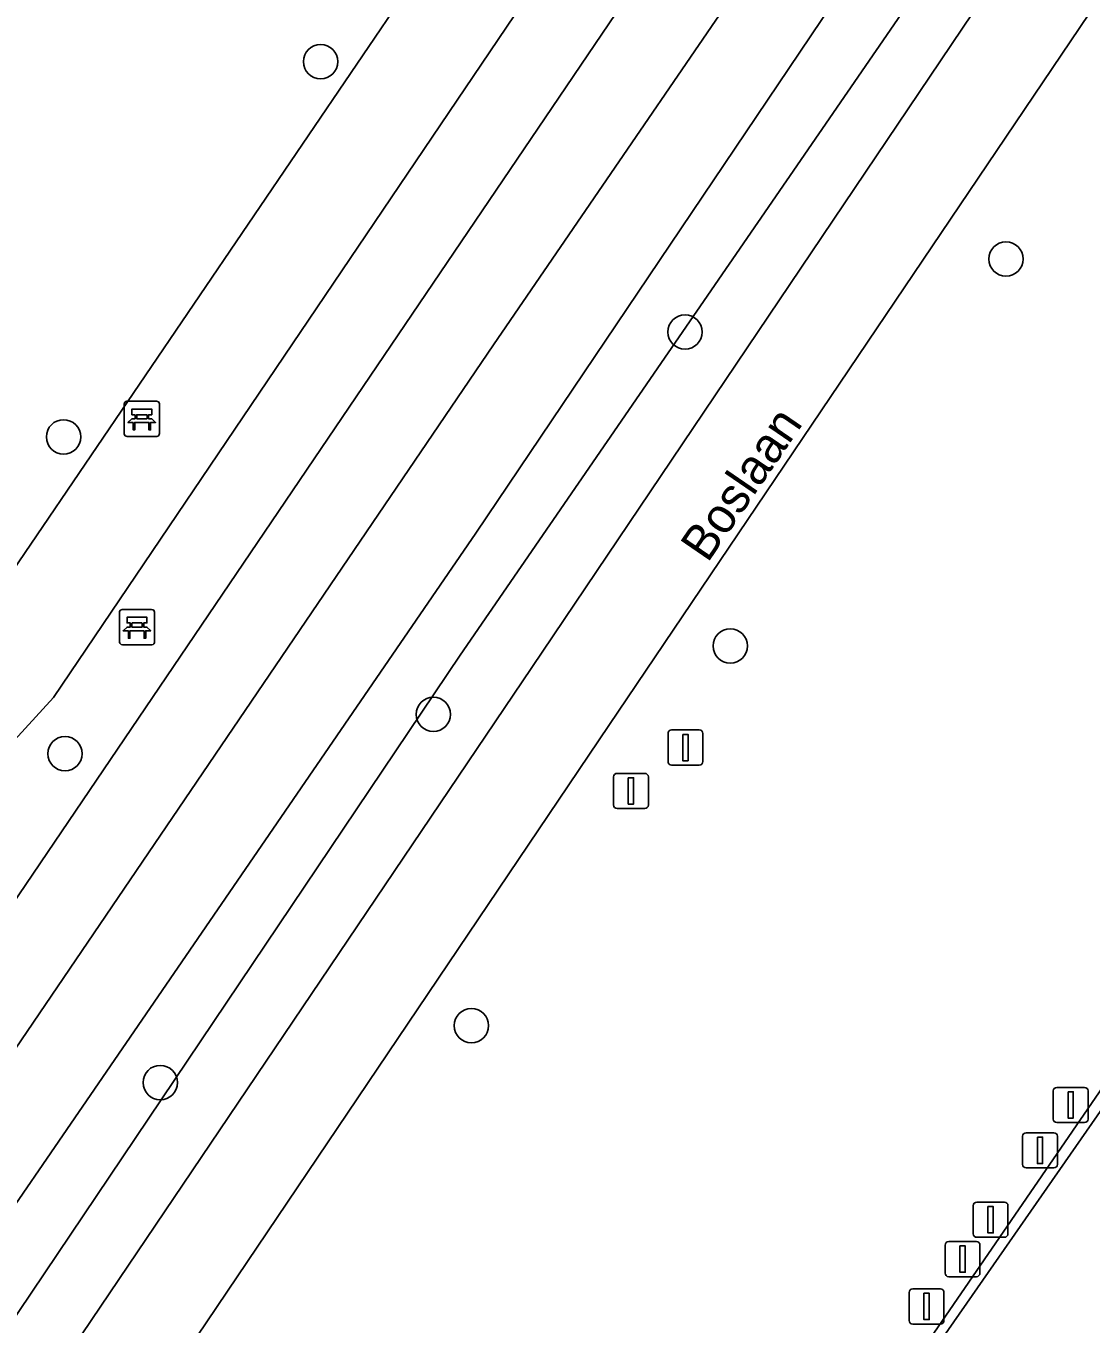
# Model space of a CAD drawing. Extents: x 157132 to 159279, y 384991 to 386650.
# Drawn here: x 159110.16 to 159140.46, y 385090.09 to 385127.03 of the extents above; entities that cross this region are included whole.
import ezdxf

# ---------------------------------------------------------------- set-up
doc = ezdxf.new("R2010")
doc.units = 0
for name, color, linetype in [('IMGEO_Afsluitpaal', 7, 'Continuous'), ('IMGEO_Bank', 7, 'Continuous'), ('IMGEO_Berm_groen', 7, 'Continuous'), ('IMGEO_Boom', 7, 'Continuous'), ('IMGEO_Gemengd_bos', 7, 'Continuous'), ('IMGEO_Grasland_overig', 7, 'Continuous'), ('IMGEO_Lichtmast', 7, 'Continuous'), ('IMGEO_Oever', 7, 'Continuous'), ('IMGEO_Openbare_ruimte_label', 7, 'Continuous'), ('IMGEO_Rijbaan_lokaal_gesloten', 7, 'Continuous'), ('IMGEO_Rijbaan_lokaal_halfverhard', 7, 'Continuous'), ('IMGEO_Voetpad_halfverhard', 7, 'Continuous'), ('IMGEO_Waterloop', 7, 'Continuous')]:
    doc.layers.add(name, color=color, linetype=linetype)

msp = doc.modelspace()

# ---------------------------------------------------------------- linework, layer by layer
at = {"layer": 'IMGEO_Afsluitpaal'}
for p, q in [((159139.391, 385095.925), (159139.391, 385096.725)), ((159139.391, 385096.725), (159139.391, 385095.925)), ((159139.491, 385096.825), (159140.281, 385096.825)), ((159140.281, 385096.825), (159139.491, 385096.825)), ((159140.381, 385096.725), (159140.381, 385095.925)), ((159140.381, 385095.925), (159140.381, 385096.725)), ((159140.281, 385095.825), (159139.491, 385095.825)), ((159139.491, 385095.825), (159140.281, 385095.825)), ((159138.518, 385094.634), (159138.518, 385095.434)), ((159138.518, 385095.434), (159138.518, 385094.634)), ((159138.618, 385095.534), (159139.408, 385095.534)), ((159139.408, 385095.534), (159138.618, 385095.534)), ((159139.508, 385095.434), (159139.508, 385094.634)), ((159139.508, 385094.634), (159139.508, 385095.434)), ((159139.408, 385094.534), (159138.618, 385094.534)), ((159138.618, 385094.534), (159139.408, 385094.534)), ((159137.112, 385092.659), (159137.112, 385093.459)), ((159137.112, 385093.459), (159137.112, 385092.659)), ((159137.212, 385093.559), (159138.002, 385093.559)), ((159138.002, 385093.559), (159137.212, 385093.559)), ((159138.102, 385093.459), (159138.102, 385092.659)), ((159138.102, 385092.659), (159138.102, 385093.459)), ((159136.315, 385091.539), (159136.315, 385092.339)), ((159136.315, 385092.339), (159136.315, 385091.539)), ((159136.415, 385092.439), (159137.205, 385092.439)), ((159137.205, 385092.439), (159136.415, 385092.439)), ((159138.002, 385092.559), (159137.212, 385092.559)), ((159137.212, 385092.559), (159138.002, 385092.559)), ((159137.305, 385092.339), (159137.305, 385091.539)), ((159137.305, 385091.539), (159137.305, 385092.339)), ((159137.205, 385091.439), (159136.415, 385091.439)), ((159136.415, 385091.439), (159137.205, 385091.439)), ((159135.29, 385090.191), (159135.29, 385090.991)), ((159135.29, 385090.991), (159135.29, 385090.191)), ((159135.39, 385091.091), (159136.18, 385091.091)), ((159136.18, 385091.091), (159135.39, 385091.091)), ((159136.28, 385090.991), (159136.28, 385090.191)), ((159136.28, 385090.191), (159136.28, 385090.991)), ((159136.18, 385090.091), (159135.39, 385090.091)), ((159135.39, 385090.091), (159136.18, 385090.091))]:
    msp.add_line(p, q, dxfattribs=at)
for points in [[(159139.811, 385096.7), (159139.961, 385096.7), (159139.961, 385095.95), (159139.811, 385095.95), (159139.811, 385096.7)], [(159138.938, 385095.409), (159139.088, 385095.409), (159139.088, 385094.659), (159138.938, 385094.659), (159138.938, 385095.409)], [(159137.532, 385093.434), (159137.682, 385093.434), (159137.682, 385092.684), (159137.532, 385092.684), (159137.532, 385093.434)], [(159136.735, 385092.314), (159136.885, 385092.314), (159136.885, 385091.564), (159136.735, 385091.564), (159136.735, 385092.314)], [(159135.71, 385090.966), (159135.86, 385090.966), (159135.86, 385090.216), (159135.71, 385090.216), (159135.71, 385090.966)]]:
    msp.add_lwpolyline(points, dxfattribs=at)
for centre, start, end in [((159139.491, 385096.725), 90, 180), ((159139.491, 385096.725), 90, 180), ((159140.281, 385096.725), 0, 90), ((159140.281, 385096.725), 360, 90), ((159139.491, 385095.925), 180, 270), ((159139.491, 385095.925), 180, 270), ((159140.281, 385095.925), 270, 0), ((159140.281, 385095.925), 270, 0), ((159138.618, 385095.434), 90, 180), ((159138.618, 385095.434), 90, 180), ((159139.408, 385095.434), 0, 90), ((159139.408, 385095.434), 360, 90), ((159138.618, 385094.634), 180, 270), ((159138.618, 385094.634), 180, 270), ((159139.408, 385094.634), 270, 0), ((159139.408, 385094.634), 270, 0), ((159137.212, 385093.459), 90, 180), ((159137.212, 385093.459), 90, 180), ((159138.002, 385093.459), 0, 90), ((159138.002, 385093.459), 360, 90), ((159137.212, 385092.659), 180, 270), ((159137.212, 385092.659), 180, 270), ((159138.002, 385092.659), 270, 0), ((159138.002, 385092.659), 270, 0), ((159136.415, 385092.339), 90, 180), ((159136.415, 385092.339), 90, 180), ((159137.205, 385092.339), 0, 90), ((159137.205, 385092.339), 360, 90), ((159136.415, 385091.539), 180, 270), ((159136.415, 385091.539), 180, 270), ((159137.205, 385091.539), 270, 0), ((159137.205, 385091.539), 270, 0), ((159135.39, 385090.991), 90, 180), ((159135.39, 385090.991), 90, 180), ((159136.18, 385090.991), 0, 90), ((159136.18, 385090.991), 360, 90), ((159135.39, 385090.191), 180, 270), ((159135.39, 385090.191), 180, 270), ((159136.18, 385090.191), 270, 0), ((159136.18, 385090.191), 270, 0)]:
    msp.add_arc(centre, 0.1, start, end, dxfattribs=at)
at = {"layer": 'IMGEO_Bank'}
for p, q in [((159112.958, 385115.424), (159112.958, 385116.265)), ((159112.958, 385116.265), (159112.958, 385115.424)), ((159113.033, 385116.349), (159113.874, 385116.349)), ((159113.874, 385116.349), (159113.033, 385116.349)), ((159113.958, 385116.274), (159113.958, 385115.433)), ((159113.958, 385115.433), (159113.958, 385116.274)), ((159113.267, 385115.855), (159113.267, 385115.961)), ((159113.311, 385115.961), (159113.311, 385115.855)), ((159113.599, 385115.967), (159113.317, 385115.967)), ((159113.605, 385115.855), (159113.605, 385115.961)), ((159113.649, 385115.961), (159113.649, 385115.855)), ((159113.655, 385115.747), (159113.262, 385115.747)), ((159113.317, 385115.849), (159113.599, 385115.849)), ((159113.883, 385115.349), (159113.042, 385115.349)), ((159113.042, 385115.349), (159113.883, 385115.349)), ((159112.896, 385110.422), (159113.737, 385110.422)), ((159113.737, 385110.422), (159112.896, 385110.422)), ((159113.821, 385110.347), (159113.821, 385109.506)), ((159113.821, 385109.506), (159113.821, 385110.347)), ((159112.821, 385109.497), (159112.821, 385110.338)), ((159112.821, 385110.338), (159112.821, 385109.497)), ((159113.13, 385109.928), (159113.13, 385110.034)), ((159113.174, 385110.034), (159113.174, 385109.928)), ((159113.462, 385110.04), (159113.18, 385110.04)), ((159113.468, 385109.928), (159113.468, 385110.034)), ((159113.512, 385110.034), (159113.512, 385109.928)), ((159113.518, 385109.82), (159113.125, 385109.82)), ((159113.18, 385109.922), (159113.462, 385109.922)), ((159113.746, 385109.422), (159112.905, 385109.422)), ((159112.905, 385109.422), (159113.746, 385109.422))]:
    msp.add_line(p, q, dxfattribs=at)
for points in [[(159113.261, 385115.967), (159113.175, 385115.967), (159113.175, 385116.128), (159113.738, 385116.128), (159113.738, 385115.967), (159113.655, 385115.967)], [(159113.205, 385115.747), (159113.063, 385115.747), (159113.175, 385115.849), (159113.261, 385115.849)], [(159113.255, 385115.74), (159113.255, 385115.533), (159113.212, 385115.533), (159113.212, 385115.74)], [(159113.655, 385115.849), (159113.738, 385115.849), (159113.85, 385115.747), (159113.711, 385115.747)], [(159113.705, 385115.74), (159113.705, 385115.533), (159113.661, 385115.533), (159113.661, 385115.74)], [(159113.124, 385110.04), (159113.038, 385110.04), (159113.038, 385110.201), (159113.601, 385110.201), (159113.601, 385110.04), (159113.518, 385110.04)], [(159113.068, 385109.82), (159112.926, 385109.82), (159113.038, 385109.922), (159113.124, 385109.922)], [(159113.118, 385109.813), (159113.118, 385109.606), (159113.075, 385109.606), (159113.075, 385109.813)], [(159113.518, 385109.922), (159113.601, 385109.922), (159113.713, 385109.82), (159113.574, 385109.82)], [(159113.568, 385109.813), (159113.568, 385109.606), (159113.524, 385109.606), (159113.524, 385109.813)]]:
    msp.add_lwpolyline(points, dxfattribs=at)
for centre, radius, start, end in [((159113.036, 385116.271), 0.0779, 92.4484, 184.2845), ((159113.036, 385116.271), 0.0779, 92.4484, 184.2845), ((159113.88, 385116.271), 0.0779, 2.4484, 94.2845), ((159113.88, 385116.271), 0.0779, 2.4484, 94.2845), ((159113.26, 385115.96), 0.00671, 2.8957, 87.1043), ((159113.317, 385115.96), 0.00671, 92.8957, 177.1043), ((159113.599, 385115.96), 0.00671, 2.8957, 87.1043), ((159113.656, 385115.96), 0.00671, 92.8957, 177.1043), ((159113.205, 385115.74), 0.00671, 2.8957, 87.1043), ((159113.262, 385115.74), 0.00671, 92.8957, 177.1043), ((159113.26, 385115.856), 0.00671, 272.8957, 357.1043), ((159113.317, 385115.856), 0.00671, 182.8957, 267.1043), ((159113.599, 385115.856), 0.00671, 272.8957, 357.1043), ((159113.656, 385115.856), 0.00671, 182.8957, 267.1043), ((159113.654, 385115.74), 0.00671, 2.8957, 87.1043), ((159113.711, 385115.74), 0.00671, 92.8957, 177.1043), ((159113.036, 385115.427), 0.0779, 182.4484, 274.2845), ((159113.036, 385115.427), 0.0779, 182.4484, 274.2845), ((159113.88, 385115.427), 0.0779, 272.4484, 4.2845), ((159113.88, 385115.427), 0.0779, 272.4484, 4.2845), ((159112.899, 385110.344), 0.0779, 92.4484, 184.2845), ((159112.899, 385110.344), 0.0779, 92.4484, 184.2845), ((159113.743, 385110.344), 0.0779, 2.4484, 94.2845), ((159113.743, 385110.344), 0.0779, 2.4484, 94.2845), ((159113.123, 385110.033), 0.00671, 2.8957, 87.1043), ((159113.18, 385110.033), 0.00671, 92.8957, 177.1043), ((159113.462, 385110.033), 0.00671, 2.8957, 87.1043), ((159113.519, 385110.033), 0.00671, 92.8957, 177.1043), ((159113.068, 385109.813), 0.00671, 2.8957, 87.1043), ((159113.125, 385109.813), 0.00671, 92.8957, 177.1043), ((159113.123, 385109.929), 0.00671, 272.8957, 357.1043), ((159113.18, 385109.929), 0.00671, 182.8957, 267.1043), ((159113.462, 385109.929), 0.00671, 272.8957, 357.1043), ((159113.519, 385109.929), 0.00671, 182.8957, 267.1043), ((159113.517, 385109.813), 0.00671, 2.8957, 87.1043), ((159113.574, 385109.813), 0.00671, 92.8957, 177.1043), ((159112.899, 385109.5), 0.0779, 182.4484, 274.2845), ((159112.899, 385109.5), 0.0779, 182.4484, 274.2845), ((159113.743, 385109.5), 0.0779, 272.4484, 4.2845), ((159113.743, 385109.5), 0.0779, 272.4484, 4.2845)]:
    msp.add_arc(centre, radius, start, end, dxfattribs=at)
at = {"layer": 'IMGEO_Berm_groen'}
for points in [[(159202.762, 385214.209), (159200.279, 385212.099), (159197.861, 385209.917), (159197.685, 385209.729), (159188.555, 385198.998), (159187.341, 385197.178), (159184.592, 385192.9), (159180.472, 385186.763), (159159.585, 385155.808), (159126.749, 385107.119), (159084.716, 385044.777), (159082.453, 385041.511)], [(159077.406, 385029.667), (159079.783, 385025.279), (159082.757, 385021.889), (159087.555, 385018.32), (159091.697, 385024.574), (159107.34, 385047.66), (159126.391, 385075.847), (159142.886, 385099.88), (159158.832, 385122.656), (159159.356, 385123.396), (159166.375, 385133.305), (159172.319, 385141.694), (159187.24, 385161.886), (159198.852, 385176.747), (159203.242, 385182.186)]]:
    msp.add_lwpolyline(points, dxfattribs=at)
at = {"layer": 'IMGEO_Boom'}
for centre in [(159118.543, 385126.012), (159138.044, 385120.396), (159128.913, 385118.319), (159111.23, 385115.335), (159130.199, 385109.386), (159121.753, 385107.439), (159111.272, 385106.32), (159122.836, 385098.582), (159113.982, 385096.963)]:
    msp.add_circle(centre, 0.489, dxfattribs=at)
at = {"layer": 'IMGEO_Gemengd_bos'}
msp.add_lwpolyline([(159105.65, 385105.454), (159139.674, 385155.54), (159093.89, 385177.901)], dxfattribs=at)
at = {"layer": 'IMGEO_Grasland_overig'}
msp.add_lwpolyline([(159098.089, 385179.186), (159097.378, 385179.59), (159094.91, 385178.395), (159093.89, 385177.901), (159139.674, 385155.54), (159105.65, 385105.454), (159098.404, 385096.707), (159088.982, 385080.864), (159077.358, 385063.69), (159069.845, 385053.174), (159071.504, 385050.354), (159072.28, 385049.465), (159088.429, 385074.259), (159094.892, 385087.522), (159100.866, 385096.897), (159110.945, 385107.918), (159129.681, 385135.667), (159170.435, 385195.371), (159173.484, 385199.281), (159170.983, 385201.616), (159141.072, 385157.596)], close=True, dxfattribs=at)
for points in [[(159178.365, 385194.724), (159173.484, 385199.281), (159170.435, 385195.371), (159129.681, 385135.667), (159110.945, 385107.918), (159100.866, 385096.897), (159094.892, 385087.522), (159088.429, 385074.259), (159072.28, 385049.465), (159074.647, 385046.84)], [(159074.812, 385050.814), (159099.176, 385086.396), (159137.123, 385142.415), (159170.631, 385192.472)], [(159076.939, 385044.887), (159078.948, 385043.251), (159079.888, 385042.589), (159124.552, 385108.774), (159157.303, 385157.398), (159178.092, 385188.144), (159178.542, 385188.806), (159179.206, 385191.452)], [(159177.304, 385190.183), (159158.739, 385162.357), (159136.9, 385130.044), (159122.513, 385109.122), (159095.149, 385068.441), (159079.233, 385045.507)]]:
    msp.add_lwpolyline(points, dxfattribs=at)
at = {"layer": 'IMGEO_Lichtmast'}
for p, q in [((159128.43, 385106.096), (159128.43, 385106.896)), ((159128.43, 385106.896), (159128.43, 385106.096)), ((159128.53, 385106.996), (159129.32, 385106.996)), ((159129.32, 385106.996), (159128.53, 385106.996)), ((159129.42, 385106.896), (159129.42, 385106.096)), ((159129.42, 385106.096), (159129.42, 385106.896)), ((159129.32, 385105.996), (159128.53, 385105.996)), ((159128.53, 385105.996), (159129.32, 385105.996)), ((159126.879, 385104.861), (159126.879, 385105.661)), ((159126.879, 385105.661), (159126.879, 385104.861)), ((159126.979, 385105.761), (159127.769, 385105.761)), ((159127.769, 385105.761), (159126.979, 385105.761)), ((159127.869, 385105.661), (159127.869, 385104.861)), ((159127.869, 385104.861), (159127.869, 385105.661)), ((159127.769, 385104.761), (159126.979, 385104.761)), ((159126.979, 385104.761), (159127.769, 385104.761))]:
    msp.add_line(p, q, dxfattribs=at)
for points in [[(159128.85, 385106.871), (159129, 385106.871), (159129, 385106.121), (159128.85, 385106.121), (159128.85, 385106.871)], [(159127.299, 385105.636), (159127.449, 385105.636), (159127.449, 385104.886), (159127.299, 385104.886), (159127.299, 385105.636)]]:
    msp.add_lwpolyline(points, dxfattribs=at)
for centre, start, end in [((159128.53, 385106.896), 90, 180), ((159128.53, 385106.896), 90, 180), ((159129.32, 385106.896), 0, 90), ((159129.32, 385106.896), 360, 90), ((159128.53, 385106.096), 180, 270), ((159128.53, 385106.096), 180, 270), ((159129.32, 385106.096), 270, 0), ((159129.32, 385106.096), 270, 0), ((159126.979, 385105.661), 90, 180), ((159126.979, 385105.661), 90, 180), ((159127.769, 385105.661), 0, 90), ((159127.769, 385105.661), 360, 90), ((159126.979, 385104.861), 180, 270), ((159126.979, 385104.861), 180, 270), ((159127.769, 385104.861), 270, 0), ((159127.769, 385104.861), 270, 0)]:
    msp.add_arc(centre, 0.1, start, end, dxfattribs=at)
at = {"layer": 'IMGEO_Oever'}
for points in [[(159170.631, 385192.472), (159137.123, 385142.415), (159099.176, 385086.396), (159074.812, 385050.814)], [(159079.233, 385045.507), (159095.149, 385068.441), (159122.513, 385109.122), (159136.9, 385130.044), (159158.739, 385162.357), (159177.304, 385190.183)], [(159156.453, 385163.154), (159141.401, 385139.978), (159122.96, 385112.597), (159097.748, 385075.847), (159079.166, 385046.919), (159078.814, 385046.638), (159078.374, 385046.564), (159076.434, 385047.649), (159076.208, 385048.03), (159076.204, 385048.403), (159076.336, 385048.723), (159076.94, 385049.624), (159088.077, 385066.264), (159104.504, 385090.052), (159123.462, 385117.952), (159132.885, 385131.714), (159147.66, 385153.943), (159156.778, 385167.227)]]:
    msp.add_lwpolyline(points, dxfattribs=at)
at = {"layer": 'IMGEO_Rijbaan_lokaal_gesloten'}
msp.add_lwpolyline([(159193.211, 385168.845), (159187.56, 385161.643), (159181.331, 385153.165), (159172.644, 385141.459), (159166.702, 385133.073), (159158.593, 385121.626), (159152.041, 385112.291), (159143.441, 385100.038), (159135.503, 385088.629), (159130.039, 385080.599), (159124.39, 385072.298), (159120.076, 385065.821), (159112.721, 385054.945), (159108.114, 385048.109)], dxfattribs=at)
at = {"layer": 'IMGEO_Rijbaan_lokaal_halfverhard'}
for points in [[(159198.852, 385176.747), (159187.24, 385161.886), (159172.319, 385141.694), (159166.375, 385133.305), (159159.356, 385123.396), (159158.832, 385122.656), (159142.886, 385099.88), (159126.391, 385075.847), (159107.34, 385047.66)], [(159108.114, 385048.109), (159112.721, 385054.945), (159120.076, 385065.821), (159124.39, 385072.298), (159130.039, 385080.599), (159135.503, 385088.629), (159143.441, 385100.038), (159152.041, 385112.291), (159158.593, 385121.626), (159166.702, 385133.073), (159172.644, 385141.459), (159181.331, 385153.165), (159187.56, 385161.643), (159193.211, 385168.845)]]:
    msp.add_lwpolyline(points, dxfattribs=at)
at = {"layer": 'IMGEO_Voetpad_halfverhard'}
for points in [[(159082.453, 385041.511), (159084.716, 385044.777), (159126.749, 385107.119), (159159.585, 385155.808), (159180.472, 385186.763), (159184.592, 385192.9), (159187.341, 385197.178), (159188.555, 385198.998), (159197.685, 385209.729), (159197.861, 385209.917), (159200.279, 385212.099), (159202.762, 385214.209)], [(159178.092, 385188.144), (159157.303, 385157.398), (159124.552, 385108.774), (159079.888, 385042.589), (159079.521, 385042.045), (159077.858, 385038.667), (159076.279, 385039.165), (159074.962, 385035.751)]]:
    msp.add_lwpolyline(points, dxfattribs=at)
at = {"layer": 'IMGEO_Waterloop'}
msp.add_lwpolyline([(159156.778, 385167.227), (159147.66, 385153.943), (159132.885, 385131.714), (159123.462, 385117.952), (159104.504, 385090.052), (159088.077, 385066.264), (159076.94, 385049.624), (159076.336, 385048.723), (159076.204, 385048.403), (159076.208, 385048.03), (159076.434, 385047.649), (159078.374, 385046.564), (159078.814, 385046.638), (159079.166, 385046.919), (159097.748, 385075.847), (159122.96, 385112.597), (159141.401, 385139.978), (159156.453, 385163.154)], dxfattribs=at)

# ---------------------------------------------------------------- texts
at = {"layer": 'IMGEO_Openbare_ruimte_label'}
msp.add_text('Boslaan', height=1, rotation=55.5948, dxfattribs=at).set_placement((159129.555, 385111.728))

doc.saveas('drawing.dxf')
